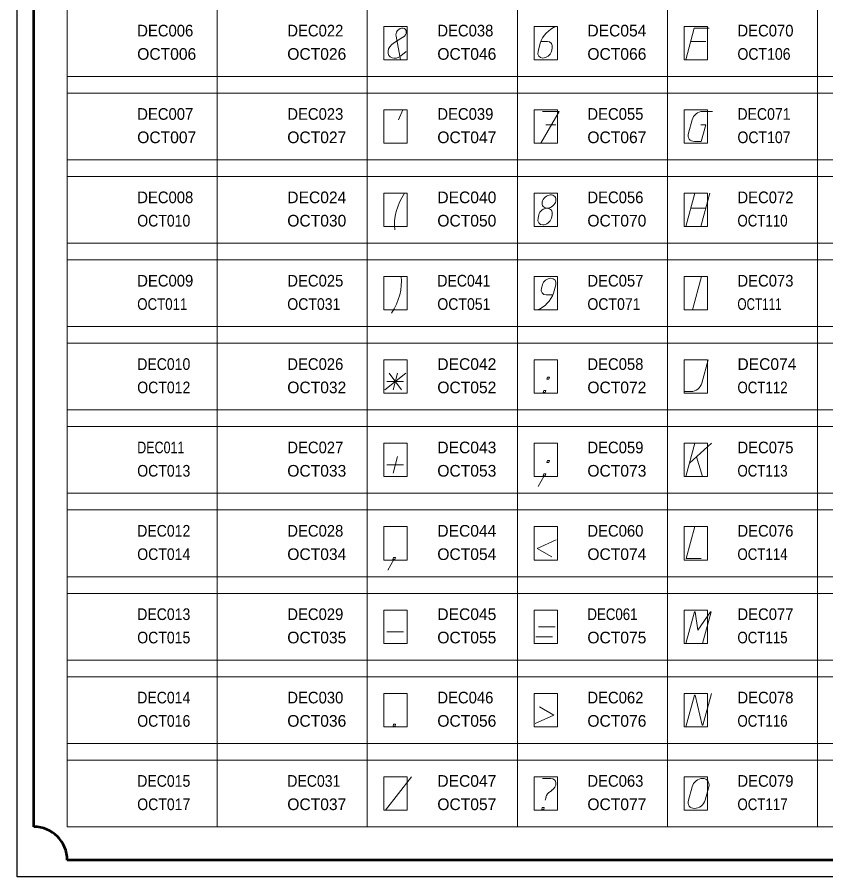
# Model space of a CAD drawing. Extents: x -200 to 7300, y -200 to 4800.
# Drawn here: x -200 to 2225, y -200 to 2378 of the extents above; entities that cross this region are included whole.
import ezdxf

# ---------------------------------------------------------------- set-up
doc = ezdxf.new("R2010")
doc.units = 0
doc.header["$LTSCALE"] = 14
for name, color, linetype, lineweight in [('1', 7, 'Continuous', 13), ('5', 7, 'Continuous', 40), ('6', 7, 'Continuous', 13), ('63', 7, 'Continuous', 13)]:
    doc.layers.add(name, color=color, linetype=linetype, lineweight=lineweight)
doc.layers.add('10', color=7, linetype='Continuous')
doc.layers.add('11', color=7, linetype='Continuous')

msp = doc.modelspace()

# ---------------------------------------------------------------- linework, layer by layer
at = {"layer": '1'}
for p, q in [((950, 2250), (937, 2321)), ((957, 2318), (928.4, 2299.7)), ((1368, 2300), (1362, 2275)), ((1370, 2305), (1390, 2305)), ((1865, 2305), (1820, 2305)), ((967, 2275), (951, 2262)), ((1404, 2285), (1402, 2275)), ((944, 2070), (957, 2100)), ((1885, 2095), (1855, 2095)), ((1824, 2070), (1813, 2030)), ((1385, 2055), (1415, 2055)), ((1832, 1850), (1805, 1750)), ((1877, 1850), (1850, 1750)), ((1820, 1805), (1865, 1805)), ((1364, 1785), (1362, 1775)), ((1404, 1785), (1402, 1775)), ((1852, 1600), (1825, 1500)), ((1372, 1565), (1375, 1575)), ((1408, 1550), (1415, 1575)), ((1406.3, 1545), (1387, 1545)), ((1853, 1280), (1872, 1350)), ((903, 1260), (966, 1310)), ((916, 1310), (953, 1260)), ((941, 1310), (928, 1260)), ((909, 1285), (959, 1285)), ((1801, 1255), (1821, 1255)), ((1832, 1100), (1805, 1000)), ((1882, 1100), (1816, 1040)), ((928, 1010), (941, 1060)), ((1837, 1059), (1855, 1000)), ((909, 1035), (959, 1035)), ((1363, 550), (1413, 550)), ((909, 535), (959, 535)), ((1355, 520), (1405, 520)), ((905, 0), (983, 100)), ((1375, 95), (1400, 95)), ((1399, 56), (1403, 59)), ((1824, 70), (1813, 30)), ((1874, 70), (1863, 30)), ((1383, 30), (1386, 39))]:
    msp.add_line(p, q, dxfattribs=at)
for points in [[(1875, 2345), (1830, 2345), (1805, 2250)], [(1375, 2095), (1425, 2095), (1370, 2000)], [(1831, 2005), (1851, 2005), (1865, 2055), (1850, 2055)], [(1380, 1002), (1377, 1002), (1379, 1008), (1385, 1008), (1383, 1002), (1380, 1002), (1362, 970)], [(1851, 755), (1806, 755), (1832, 850)], [(1416, 810), (1359, 785), (1403, 760)], [(930, 752), (927, 752), (929, 758), (935, 758), (933, 752), (930, 752), (912, 720)], [(1805, 500), (1831, 595), (1833, 595), (1841, 540), (1879, 595), (1881, 595), (1855, 500)], [(1805, 250), (1831, 345), (1833, 345), (1854, 255), (1856, 255), (1882, 350)], [(1366, 310), (1409, 285), (1353, 260)]]:
    msp.add_lwpolyline(points, dxfattribs=at)
for points in [[(1388, 1292), (1394, 1292), (1396, 1298), (1390, 1298)], [(1377, 1252), (1383, 1252), (1385, 1258), (1379, 1258)], [(1388, 1042), (1394, 1042), (1396, 1048), (1390, 1048)], [(928, 252), (934, 252), (935, 258), (929, 258)], [(1373, 2), (1379, 2), (1380, 8), (1374, 8)]]:
    msp.add_lwpolyline(points, close=True, dxfattribs=at)
for centre, major_axis, ratio, start_param, end_param in [((1423.85, 2297.95), (-48.32, -42.27), 0.765566, 4.2461946, 5.3948042), ((951.29, 2330), (-12.9, -11.29), 0.765566, 1.3623375, 6.0890323), ((938.06, 2279.68), (-21.5, -18.81), 0.767096, 4.5039301, 7.7874198), ((1384, 2285), (-17.2, -15.05), 0.765566, 2.2896327, 3.860429), ((1382, 2275), (17.2, 15.05), 0.765566, 2.2896328, 5.4312254), ((1849, 2070), (-21.5, -18.81), 0.765566, 3.860429, 5.4312252), ((1838, 2030), (21.5, 18.81), 0.765566, 2.2896328, 3.860429), ((1091.95, 1795), (133.39, 116.71), 0.765566, 1.9270883, 2.6521768), ((1384, 1785), (-17.2, -15.05), 0.765566, 2.2896326, 5.4312252), ((1382, 1775), (17.2, 15.05), 0.765566, 2.2896328, 5.4312254), ((791.96, 1545), (133.39, 116.71), 0.765566, 5.0686811, 5.7937695), ((1395.01, 1575), (-17.2, -15.05), 0.765566, 2.2896326, 5.4312252), ((1352.41, 1552.05), (48.32, 42.27), 0.765566, 4.2461945, 5.3948041), ((1392, 1565), (17.2, 15.05), 0.765566, 2.2896327, 3.860429), ((1828, 1280), (-21.5, -18.81), 0.765566, 0.7188363, 2.2896326), ((1395.1, 75), (-17.2, -15.05), 0.765566, 1.3623374, 3.860429), ((1849, 70), (-21.5, -18.81), 0.765566, 2.2896326, 5.4312252), ((1405.54, 39.3), (-17.2, -15.05), 0.765566, 4.4484316, 5.4312253), ((1838, 30), (21.5, 18.81), 0.765566, 2.2896328, 5.4312254)]:
    msp.add_ellipse(centre, major_axis=major_axis, ratio=ratio, start_param=start_param, end_param=end_param, dxfattribs=at)
msp.add_ellipse((1394.99, 1825), major_axis=(-17.2, -15.05), ratio=0.765566, dxfattribs=at)
at = {"layer": '5', "lineweight": 53}
for p, q in [((-150, -50), (-150, 4650)), ((7150, -150), (-50, -150))]:
    msp.add_line(p, q, dxfattribs=at)
at = {"layer": '5', "lineweight": 25}
msp.add_lwpolyline([(-200, -200), (-200, 4800), (7300, 4800), (7300, -200)], close=True, dxfattribs=at)
at = {"layer": '5', "lineweight": 53}
msp.add_arc((-150, -150), 100, 0, 90, dxfattribs=at)
at = {"layer": '6'}
for p, q in [((-50, 3950), (-50, -50)), ((400, 3950), (400, -50)), ((850, 3950), (850, -50)), ((1300, 3950), (1300, -50)), ((1750, 3950), (1750, -50)), ((2200, 3950), (2200, -50)), ((-50, 2200), (7150, 2200)), ((-50, 2150), (7150, 2150)), ((-50, 1950), (7150, 1950)), ((-50, 1900), (7150, 1900)), ((-50, 1700), (7150, 1700)), ((-50, 1650), (7150, 1650)), ((-50, 1450), (7150, 1450)), ((-50, 1400), (7150, 1400)), ((-50, 1200), (7150, 1200)), ((-50, 1150), (7150, 1150)), ((-50, 950), (7150, 950)), ((-50, 900), (7150, 900)), ((-50, 700), (7150, 700)), ((-50, 650), (7150, 650)), ((-50, 450), (7150, 450)), ((-50, 400), (7150, 400)), ((-50, 200), (7150, 200)), ((-50, 150), (7150, 150)), ((-50, -50), (7150, -50))]:
    msp.add_line(p, q, dxfattribs=at)
at = {"layer": '63'}
for points in [[(900, 2250), (970, 2250), (970, 2350), (900, 2350)], [(1350, 2250), (1420, 2250), (1420, 2350), (1350, 2350)], [(1800, 2250), (1870, 2250), (1870, 2350), (1800, 2350)], [(900, 2000), (970, 2000), (970, 2100), (900, 2100)], [(1350, 2000), (1420, 2000), (1420, 2100), (1350, 2100)], [(1800, 2000), (1870, 2000), (1870, 2100), (1800, 2100)], [(900, 1750), (970, 1750), (970, 1850), (900, 1850)], [(1350, 1750), (1420, 1750), (1420, 1850), (1350, 1850)], [(1800, 1750), (1870, 1750), (1870, 1850), (1800, 1850)], [(900, 1500), (970, 1500), (970, 1600), (900, 1600)], [(1350, 1500), (1420, 1500), (1420, 1600), (1350, 1600)], [(1800, 1500), (1870, 1500), (1870, 1600), (1800, 1600)], [(900, 1250), (970, 1250), (970, 1350), (900, 1350)], [(1350, 1250), (1420, 1250), (1420, 1350), (1350, 1350)], [(1800, 1250), (1870, 1250), (1870, 1350), (1800, 1350)], [(900, 1000), (970, 1000), (970, 1100), (900, 1100)], [(1350, 1000), (1420, 1000), (1420, 1100), (1350, 1100)], [(1800, 1000), (1870, 1000), (1870, 1100), (1800, 1100)], [(900, 750), (970, 750), (970, 850), (900, 850)], [(1350, 750), (1420, 750), (1420, 850), (1350, 850)], [(1800, 750), (1870, 750), (1870, 850), (1800, 850)], [(900, 500), (970, 500), (970, 600), (900, 600)], [(1350, 500), (1420, 500), (1420, 600), (1350, 600)], [(1800, 500), (1870, 500), (1870, 600), (1800, 600)], [(900, 250), (970, 250), (970, 350), (900, 350)], [(1350, 250), (1420, 250), (1420, 350), (1350, 350)], [(1800, 250), (1870, 250), (1870, 350), (1800, 350)], [(900, 0), (970, 0), (970, 100), (900, 100)], [(1350, 0), (1420, 0), (1420, 100), (1350, 100)], [(1800, 0), (1870, 0), (1870, 100), (1800, 100)]]:
    msp.add_lwpolyline(points, close=True, dxfattribs=at)

# ---------------------------------------------------------------- texts
at = {"layer": '10'}
for s, width, p in [('DEC006', 0.95, (160, 2320)), ('DEC022', 0.95, (610, 2320)), ('DEC038', 0.95, (1060, 2320)), ('DEC070', 0.95, (1960, 2320)), ('DEC007', 0.95, (160, 2070)), ('DEC023', 0.95, (610, 2070)), ('DEC039', 0.95, (1060, 2070)), ('DEC055', 0.95, (1510, 2070)), ('DEC071', 0.9, (1960, 2070)), ('DEC008', 0.95, (160, 1820)), ('DEC056', 0.95, (1510, 1820)), ('DEC072', 0.95, (1960, 1820)), ('DEC009', 0.95, (160, 1570)), ('DEC025', 0.95, (610, 1570)), ('DEC041', 0.9, (1060, 1570)), ('DEC057', 0.95, (1510, 1570)), ('DEC073', 0.95, (1960, 1570)), ('DEC010', 0.9, (160, 1320)), ('DEC026', 0.95, (610, 1320)), ('DEC058', 0.95, (1510, 1320)), ('DEC011', 0.8, (160, 1070)), ('DEC027', 0.95, (610, 1070)), ('DEC059', 0.95, (1510, 1070)), ('DEC075', 0.95, (1960, 1070)), ('DEC012', 0.9, (160, 820)), ('DEC028', 0.95, (610, 820)), ('DEC060', 0.95, (1510, 820)), ('DEC076', 0.95, (1960, 820)), ('DEC013', 0.9, (160, 570)), ('DEC029', 0.95, (610, 570)), ('DEC061', 0.85, (1510, 570)), ('DEC077', 0.95, (1960, 570)), ('DEC014', 0.9, (160, 320)), ('DEC030', 0.95, (610, 320)), ('DEC046', 0.95, (1060, 320)), ('DEC062', 0.95, (1510, 320)), ('DEC078', 0.95, (1960, 320)), ('DEC015', 0.9, (160, 70)), ('DEC031', 0.9, (610, 70)), ('DEC063', 0.95, (1510, 70)), ('DEC079', 0.95, (1960, 70))]:
    msp.add_text(s, height=35, dxfattribs=dict(at, width=width)).set_placement(p)
for s, p in [('DEC054', (1510, 2320)), ('DEC024', (610, 1820)), ('DEC040', (1060, 1820)), ('DEC042', (1060, 1320)), ('DEC074', (1960, 1320)), ('DEC043', (1060, 1070)), ('DEC044', (1060, 820)), ('DEC045', (1060, 570)), ('DEC047', (1060, 70))]:
    msp.add_text(s, height=35, dxfattribs=at).set_placement(p)
at = {"layer": '11'}
for s, p in [('OCT006', (160, 2250)), ('OCT026', (610, 2250)), ('OCT046', (1060, 2250)), ('OCT066', (1510, 2250)), ('OCT007', (160, 2000)), ('OCT027', (610, 2000)), ('OCT047', (1060, 2000)), ('OCT067', (1510, 2000)), ('OCT030', (610, 1750)), ('OCT050', (1060, 1750)), ('OCT070', (1510, 1750)), ('OCT032', (610, 1250)), ('OCT052', (1060, 1250)), ('OCT072', (1510, 1250)), ('OCT033', (610, 1000)), ('OCT053', (1060, 1000)), ('OCT073', (1510, 1000)), ('OCT034', (610, 750)), ('OCT054', (1060, 750)), ('OCT074', (1510, 750)), ('OCT035', (610, 500)), ('OCT055', (1060, 500)), ('OCT075', (1510, 500)), ('OCT036', (610, 250)), ('OCT056', (1060, 250)), ('OCT076', (1510, 250)), ('OCT037', (610, 0)), ('OCT057', (1060, 0)), ('OCT077', (1510, 0))]:
    msp.add_text(s, height=35, dxfattribs=at).set_placement(p)
for s, width, p in [('OCT106', 0.9, (1960, 2250)), ('OCT107', 0.9, (1960, 2000)), ('OCT010', 0.9, (160, 1750)), ('OCT110', 0.85, (1960, 1750)), ('OCT011', 0.85, (160, 1500)), ('OCT031', 0.9, (610, 1500)), ('OCT051', 0.9, (1060, 1500)), ('OCT071', 0.9, (1510, 1500)), ('OCT111', 0.75, (1960, 1500)), ('OCT012', 0.9, (160, 1250)), ('OCT112', 0.85, (1960, 1250)), ('OCT013', 0.9, (160, 1000)), ('OCT113', 0.85, (1960, 1000)), ('OCT014', 0.9, (160, 750)), ('OCT114', 0.85, (1960, 750)), ('OCT015', 0.9, (160, 500)), ('OCT115', 0.85, (1960, 500)), ('OCT016', 0.9, (160, 250)), ('OCT116', 0.85, (1960, 250)), ('OCT017', 0.9, (160, 0)), ('OCT117', 0.85, (1960, 0))]:
    msp.add_text(s, height=35, dxfattribs=dict(at, width=width)).set_placement(p)

doc.saveas('drawing.dxf')
